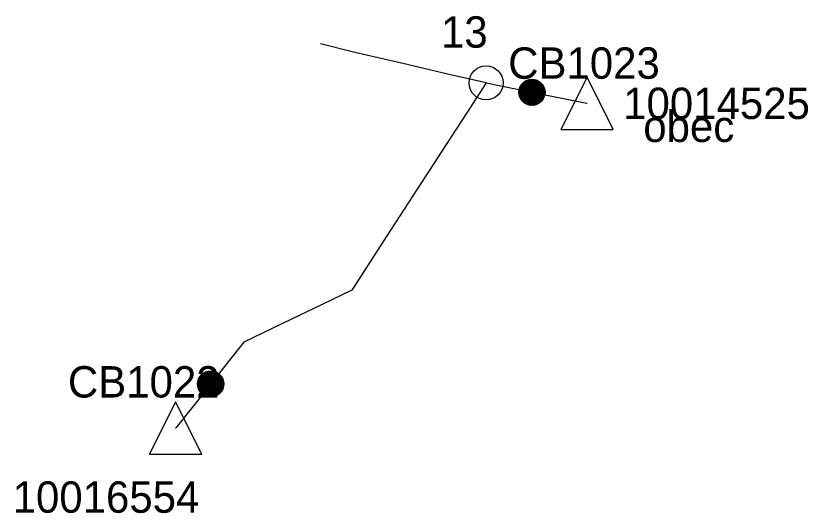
# Model space of a CAD drawing. Extents: x -749194 to -734612, y -1146817 to -1138558.
# Drawn here: x -748600 to -747085, y -1141068 to -1140116 of the extents above; entities that cross this region are included whole.
import ezdxf

# ---------------------------------------------------------------- set-up
doc = ezdxf.new("R2010")
doc.units = 0
for name, color, linetype in [('Default', 7, 'Continuous'), ('Vrstva 1', 7, 'Continuous'), ('Vrstva 2', 7, 'Continuous'), ('Vrstva 3', 7, 'Continuous'), ('Vrstva 44', 7, 'Continuous'), ('Vrstva 5', 7, 'Continuous')]:
    doc.layers.add(name, color=color, linetype=linetype)

# ---------------------------------------------------------------- blocks, each defined once
blk = doc.blocks.new('PS440')
at = {"layer": 'Default'}
for p, q in [((-25, 0.1), (-0.1, 25)), ((-24.9, -1.2), (1.2, 24.9)), ((-24.9, 1.6), (-1.6, 24.9)), ((-24.8, -2.6), (2.6, 24.8)), ((-24.8, 3.2), (-3.2, 24.8)), ((-24.7, -3.8), (3.8, 24.7)), ((-24.5, -5), (5, 24.5)), ((-24.5, 4.9), (-4.9, 24.5)), ((-24.2, -6.2), (6.2, 24.2)), ((-24.1, 6.7), (-6.7, 24.1)), ((-23.9, -7.3), (7.3, 23.9)), ((-23.6, -8.3), (8.3, 23.6)), ((-23.4, 8.8), (-8.8, 23.4)), ((-23.2, -9.4), (9.4, 23.2)), ((-22.7, -10.3), (10.3, 22.7)), ((-22.3, -11.3), (11.3, 22.3)), ((-22.3, 11.3), (-11.3, 22.3)), ((-21.8, -12.2), (12.2, 21.8)), ((-21.3, -13.1), (13.1, 21.3)), ((-20.7, -14), (14, 20.7)), ((-20.1, -14.8), (14.8, 20.1)), ((-19.9, 15.2), (-15.2, 19.9)), ((-19.5, -15.6), (15.6, 19.5)), ((-18.9, -16.4), (16.4, 18.9)), ((-18.2, -17.1), (17.1, 18.2)), ((-17.5, -17.8), (17.8, 17.5)), ((-16.8, -18.5), (18.5, 16.8)), ((-16, -19.2), (19.2, 16)), ((-15.2, -19.8), (19.8, 15.2)), ((-14.4, -20.4), (20.4, 14.4)), ((-13.6, -21), (21, 13.6)), ((-12.7, -21.5), (21.5, 12.7)), ((-11.8, -22), (22, 11.8)), ((-10.8, -22.5), (22.5, 10.8)), ((-9.9, -22.9), (22.9, 9.9)), ((-8.9, -23.4), (23.4, 8.9)), ((-7.8, -23.7), (23.7, 7.8)), ((-6.7, -24.1), (24.1, 6.7)), ((-5.6, -24.3), (24.3, 5.6)), ((-4.4, -24.6), (24.6, 4.4)), ((-3.2, -24.8), (24.8, 3.2)), ((-1.9, -24.9), (24.9, 1.9)), ((-0.6, -25), (25, 0.6)), ((0.8, -25), (25, -0.8)), ((2.3, -24.9), (24.9, -2.3)), ((4, -24.7), (24.7, -4)), ((5.7, -24.3), (24.3, -5.7)), ((7.7, -23.8), (23.8, -7.7)), ((10, -22.9), (22.9, -10)), ((12.9, -21.4), (21.4, -12.9))]:
    blk.add_line(p, q, dxfattribs=at)
blk.add_circle((0, 0), 25, dxfattribs=at)
blk = doc.blocks.new('PS820')
at = {"layer": 'Vrstva 2'}
blk.add_circle((0, 0), 32.5, dxfattribs=at)
blk = doc.blocks.new('PS685')
at = {"layer": 'Vrstva 44'}
for points in [[(-0.1, 50.1), (-50.1, -49.9)], [(49.9, -49.9), (-0.1, 50.1)], [(-50.1, -49.9), (49.9, -49.9)]]:
    blk.add_lwpolyline(points, dxfattribs=at)

msp = doc.modelspace()

# ---------------------------------------------------------------- linework, layer by layer
at = {"layer": 'Vrstva 1'}
for points in [[(-747700.7, -1140244.7), (-747776.7, -1140227.1), (-747862.7, -1140207.1), (-747951.4, -1140186.4), (-748017.5, -1140170.2)], [(-747700.7, -1140244.7), (-747737.7, -1140301.8), (-747777.2, -1140362.7), (-747832.3, -1140447.8), (-747890.4, -1140537.5), (-747957.6, -1140641.2), (-748013.8, -1140668.4), (-748088.6, -1140704.5), (-748163.9, -1140740.9), (-748193.7, -1140778.4), (-748227.2, -1140820.6), (-748227.2, -1140820.6)], [(-747700.7, -1140244.7), (-747700.7, -1140244.7), (-747700.7, -1140244.7), (-747613, -1140262.5)], [(-747613, -1140262.5), (-747613, -1140262.5), (-747508.2, -1140283.7), (-747507.5, -1140283.9)], [(-748227.2, -1140820.6), (-748227.2, -1140820.6), (-748227.2, -1140820.7), (-748293.2, -1140903.7), (-748294.2, -1140904.9)]]:
    msp.add_lwpolyline(points, dxfattribs=at)

# ---------------------------------------------------------------- block references
at = {"layer": 'Vrstva 2'}
for p, rotation in [((-747613, -1140262.5), -10.99999982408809), ((-748227.2, -1140820.6), 52.00000007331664)]:
    msp.add_blockref('PS440', p, dxfattribs=dict(at, rotation=rotation))
at = {"layer": 'Vrstva 3'}
for p in [(-747507.5, -1140283.9), (-748294.2, -1140904.9)]:
    msp.add_blockref('PS685', p, dxfattribs=at)
at = {"layer": 'Vrstva 5', "rotation": -13.000000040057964}
msp.add_blockref('PS820', (-747700.7, -1140244.7), dxfattribs=at)

# ---------------------------------------------------------------- texts
at = {"layer": 'Vrstva 2'}
for s, p in [('CB1023', (-747658.4, -1140236.7)), ('CB1022', (-748500.2, -1140846.5))]:
    msp.add_text(s, height=60, dxfattribs=at).set_placement(p)
at = {"layer": 'Vrstva 3'}
for s, p in [('10014525', (-747438.5, -1140313.7)), ('obec', (-747400.1, -1140357.7)), ('10016554', (-748605.9, -1141066.9))]:
    msp.add_text(s, height=60, dxfattribs=at).set_placement(p)
at = {"layer": 'Vrstva 5'}
msp.add_text('13', height=60, dxfattribs=at).set_placement((-747786.9, -1140177.2))

doc.saveas('drawing.dxf')
